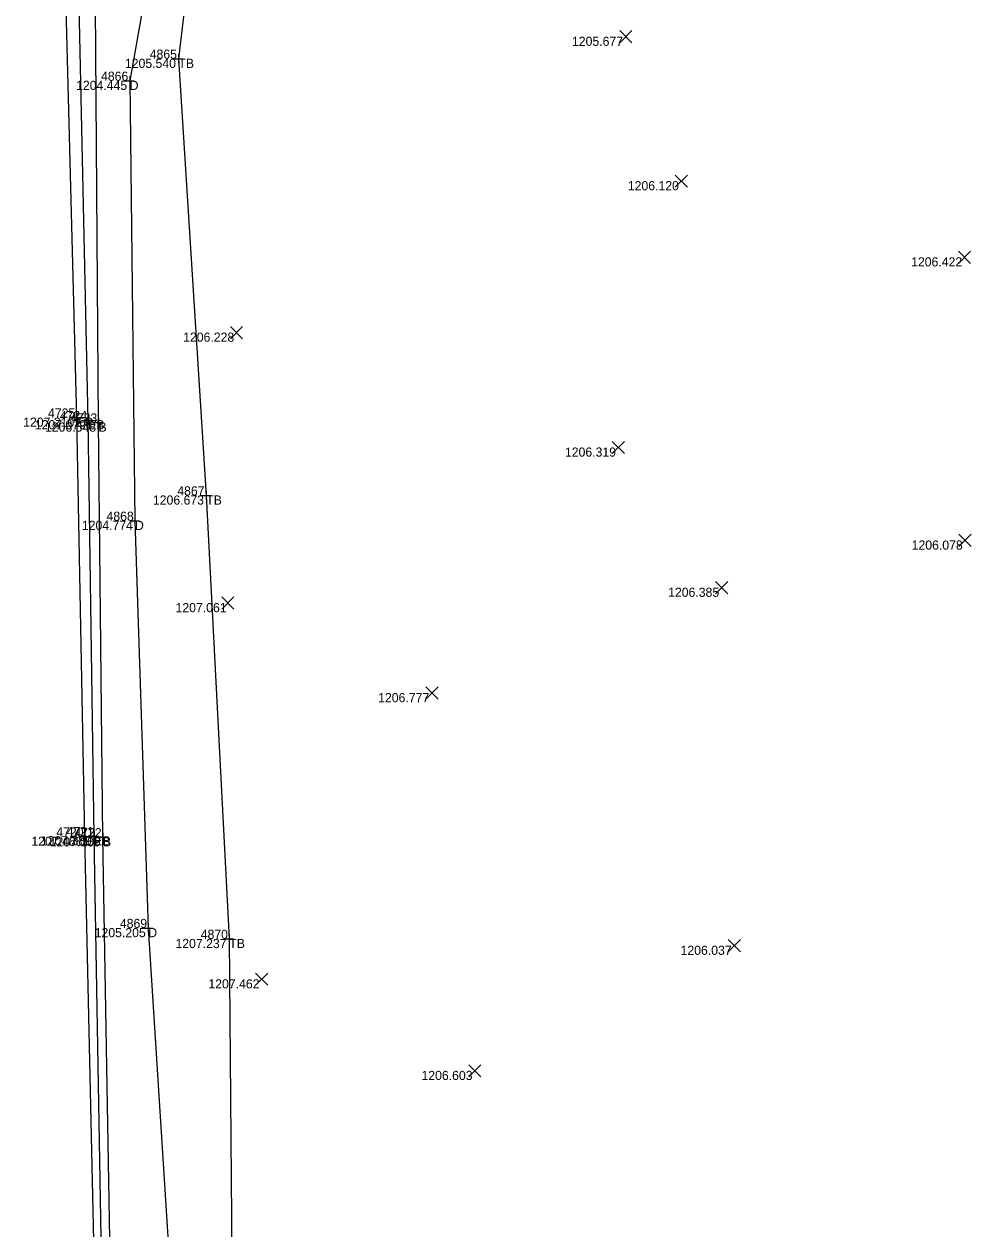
# Model space of a CAD drawing. Extents: x 2044996 to 2050343, y 455232 to 458054.
# Drawn here: x 2047639.9 to 2047743.9, y 456784 to 456915.7 of the extents above; entities that cross this region are included whole.
import ezdxf

# ---------------------------------------------------------------- set-up
doc = ezdxf.new("R2010")
doc.units = 0
for name, color, linetype in [('DR_X_Ditch', 7, 'Continuous'), ('DT_X_Contour_Minor', 7, 'Continuous'), ('DT_X_Contour_Text', 7, 'Continuous'), ('DT_X_Spot_Elev', 7, 'Continuous'), ('DT_X_Triangles', 7, 'Continuous'), ('DT_X_Void', 7, 'Continuous'), ('PV_X_EOP', 7, 'Continuous'), ('PV_X_Shoulder_Aggregate', 7, 'Continuous'), ('SV_X_Break_Lines', 7, 'Continuous'), ('SV_X_Top_of_Bank', 7, 'Continuous')]:
    doc.layers.add(name, color=color, linetype=linetype)

msp = doc.modelspace()

# ---------------------------------------------------------------- linework, layer by layer
at = {"layer": 'DR_X_Ditch'}
msp.add_lwpolyline([(2047944.96, 456861.76), (2047899.25, 456878.16), (2047861.64, 456891.96), (2047815.35, 456909.09), (2047774.86, 456921.86), (2047729.93, 456938.25), (2047691.42, 456950.76), (2047669.22, 456956.37), (2047658.75, 456950.98), (2047651.4, 456909.49), (2047651.98, 456861.4), (2047653.43, 456816.89), (2047656.94, 456761.43), (2047657.83, 456718.94), (2047659.36, 456677.43), (2047660.77, 456628.12), (2047661.37, 456577.1), (2047662.68, 456519.59), (2047665.25, 456466.46), (2047666.16, 456418.54), (2047665.56, 456406.95)], dxfattribs=at)
at = {"layer": 'DT_X_Spot_Elev'}
for p, q in [((2047704.92, 456913.64), (2047706.26, 456914.98)), ((2047704.92, 456914.98), (2047706.26, 456913.64)), ((2047710.98, 456897.86), (2047712.31, 456899.19)), ((2047710.98, 456899.19), (2047712.31, 456897.86)), ((2047741.91, 456889.53), (2047743.25, 456890.87)), ((2047741.91, 456890.87), (2047743.25, 456889.53)), ((2047662.41, 456881.3), (2047663.74, 456882.64)), ((2047662.41, 456882.64), (2047663.74, 456881.3)), ((2047704.1, 456868.74), (2047705.43, 456870.08)), ((2047704.1, 456870.08), (2047705.43, 456868.74)), ((2047741.98, 456858.59), (2047743.31, 456859.92)), ((2047741.98, 456859.92), (2047743.31, 456858.59)), ((2047715.39, 456853.43), (2047716.73, 456854.76)), ((2047715.39, 456854.76), (2047716.73, 456853.43)), ((2047661.46, 456851.75), (2047662.79, 456853.08)), ((2047661.46, 456853.08), (2047662.79, 456851.75)), ((2047683.75, 456841.91), (2047685.08, 456843.24)), ((2047683.75, 456843.24), (2047685.08, 456841.91)), ((2047716.78, 456814.29), (2047718.11, 456815.63)), ((2047716.78, 456815.63), (2047718.11, 456814.29)), ((2047665.16, 456810.63), (2047666.5, 456811.96)), ((2047665.16, 456811.96), (2047666.5, 456810.63)), ((2047688.43, 456800.61), (2047689.76, 456801.95)), ((2047688.43, 456801.95), (2047689.76, 456800.61))]:
    msp.add_line(p, q, dxfattribs=at)
at = {"layer": 'DT_X_Void'}
for p, q in [((2047656.22, 456911.9), (2047657.22, 456911.9)), ((2047656.72, 456912.4), (2047656.72, 456911.4)), ((2047656.72, 456911.9), (2047656.72, 456911.9)), ((2047651.4, 456909.99), (2047651.4, 456908.99)), ((2047650.9, 456909.49), (2047651.9, 456909.49)), ((2047651.4, 456909.49), (2047651.4, 456909.49)), ((2047645.61, 456873.18), (2047645.61, 456872.18)), ((2047645.11, 456872.68), (2047646.11, 456872.68)), ((2047645.61, 456872.68), (2047645.61, 456872.68)), ((2047646.36, 456872.4), (2047647.36, 456872.4)), ((2047646.86, 456872.9), (2047646.86, 456871.9)), ((2047646.86, 456872.4), (2047646.86, 456872.4)), ((2047647.49, 456872.14), (2047648.49, 456872.14)), ((2047647.99, 456872.64), (2047647.99, 456871.64)), ((2047647.99, 456872.14), (2047647.99, 456872.14)), ((2047659.26, 456864.17), (2047660.26, 456864.17)), ((2047659.76, 456864.67), (2047659.76, 456863.67)), ((2047659.76, 456864.17), (2047659.76, 456864.17)), ((2047651.48, 456861.4), (2047652.48, 456861.4)), ((2047651.98, 456861.9), (2047651.98, 456860.9)), ((2047651.98, 456861.4), (2047651.98, 456861.4)), ((2047646.5, 456827.38), (2047646.5, 456826.38)), ((2047647.51, 456827.43), (2047647.51, 456826.43)), ((2047648.48, 456827.31), (2047648.48, 456826.31)), ((2047646, 456826.88), (2047647, 456826.88)), ((2047646.5, 456826.88), (2047646.5, 456826.88)), ((2047647.01, 456826.93), (2047648.01, 456826.93)), ((2047647.51, 456826.93), (2047647.51, 456826.93)), ((2047647.98, 456826.81), (2047648.98, 456826.81)), ((2047648.48, 456826.81), (2047648.48, 456826.81)), ((2047652.93, 456816.89), (2047653.93, 456816.89)), ((2047653.43, 456817.39), (2047653.43, 456816.39)), ((2047653.43, 456816.89), (2047653.43, 456816.89)), ((2047661.78, 456815.7), (2047662.78, 456815.7)), ((2047662.28, 456816.2), (2047662.28, 456815.2)), ((2047662.28, 456815.7), (2047662.28, 456815.7))]:
    msp.add_line(p, q, dxfattribs=at)
at = {"layer": 'PV_X_EOP'}
for p, q in [((2047645.61, 456872.68), (2047644.48, 456917.41)), ((2047646.5, 456826.88), (2047645.61, 456872.68)), ((2047647.56, 456778.58), (2047646.5, 456826.88))]:
    msp.add_line(p, q, dxfattribs=at)
at = {"layer": 'PV_X_Shoulder_Aggregate'}
msp.add_lwpolyline([(2047651.94, 456638.93), (2047650.86, 456688.18), (2047649.6, 456733), (2047648.37, 456778.91), (2047647.51, 456826.93), (2047646.86, 456872.4), (2047645.87, 456917.72), (2047645.01, 456938.98), (2047644.95, 456952.82), (2047645.89, 456959.85), (2047646.68, 456960.97), (2047650.24, 456962.76), (2047655.73, 456966.3), (2047657.7, 456966.84), (2047664.7, 456965.75), (2047672.59, 456964.54), (2047677.71, 456963.33), (2047718.66, 456948.27), (2047759.49, 456933.93)], dxfattribs=at)
at = {"layer": 'SV_X_Break_Lines'}
msp.add_lwpolyline([(2047658.43, 456406.25), (2047657.57, 456454.16), (2047657.12, 456499.13), (2047656.02, 456546.18), (2047654.76, 456590.52), (2047653.67, 456638.77), (2047652.84, 456687.95), (2047651.32, 456732.84), (2047649.31, 456778.74), (2047648.48, 456826.81), (2047647.99, 456872.14), (2047647.65, 456917.64), (2047648.11, 456940.22), (2047652.79, 456955.84)], dxfattribs=at)
at = {"layer": 'SV_X_Top_of_Bank'}
msp.add_lwpolyline([(2047942.14, 456857.99), (2047898.01, 456872.36), (2047859.06, 456885.19), (2047815.47, 456901.27), (2047771.85, 456916.42), (2047729.97, 456932.49), (2047688.22, 456947.3), (2047669.99, 456955.17), (2047661.07, 456948.62), (2047656.72, 456911.9), (2047659.76, 456864.17), (2047662.28, 456815.7), (2047662.72, 456763.39), (2047662.48, 456719.38), (2047665.2, 456677.14), (2047665.7, 456629.87), (2047667.28, 456578.15), (2047668.69, 456520.88), (2047669.88, 456466.8), (2047671, 456408.28)], dxfattribs=at)

# ---------------------------------------------------------------- texts
at = {"layer": 'DT_X_Contour_Minor'}
for s, p in [('1205.677', (2047699.71, 456913.31)), ('1205.540', (2047650.88, 456910.9)), ('1204.445', (2047645.55, 456908.49)), ('1206.120', (2047705.81, 456897.52)), ('1206.422', (2047736.75, 456889.2)), ('1206.228', (2047657.24, 456880.97)), ('1207.210', (2047639.77, 456871.68)), ('1207.079', (2047641.04, 456871.4)), ('1206.548', (2047642.15, 456871.14)), ('1206.319', (2047698.94, 456868.41)), ('1206.673', (2047653.94, 456863.17)), ('1204.774', (2047646.18, 456860.4)), ('1206.078', (2047736.81, 456858.25)), ('1206.385', (2047710.21, 456853.09)), ('1207.061', (2047656.41, 456851.41)), ('1206.777', (2047678.54, 456841.57)), ('1207.488', (2047640.66, 456825.88)), ('1207.389', (2047641.69, 456825.93)), ('1207.109', (2047642.66, 456825.81)), ('1205.205', (2047647.58, 456815.89)), ('1207.237', (2047656.4, 456814.7)), ('1206.037', (2047711.57, 456813.96)), ('1207.462', (2047660, 456810.29)), ('1206.603', (2047683.27, 456800.28))]:
    msp.add_text(s, height=1, dxfattribs=at).set_placement(p)
at = {"layer": 'DT_X_Contour_Text'}
for s, p in [('TB', (2047656.72, 456910.9)), ('D', (2047651.4, 456908.49)), ('EP', (2047645.61, 456871.68)), ('EB', (2047646.86, 456871.4)), ('B', (2047647.99, 456871.14)), ('TB', (2047659.76, 456863.17)), ('D', (2047651.98, 456860.4)), ('EP', (2047646.5, 456825.88)), ('EB', (2047647.51, 456825.93)), ('B', (2047648.48, 456825.81)), ('D', (2047653.43, 456815.89)), ('TB', (2047662.28, 456814.7))]:
    msp.add_text(s, height=1, dxfattribs=at).set_placement(p)
at = {"layer": 'DT_X_Triangles'}
for s, p in [('4865', (2047653.59, 456911.9)), ('4866', (2047648.27, 456909.49)), ('4725', (2047642.48, 456872.68)), ('4724', (2047643.77, 456872.4)), ('4723', (2047644.88, 456872.14)), ('4867', (2047656.6, 456864.17)), ('4868', (2047648.87, 456861.4)), ('4720', (2047643.38, 456826.88)), ('4721', (2047644.51, 456826.93)), ('4722', (2047645.36, 456826.81)), ('4869', (2047650.33, 456816.89)), ('4870', (2047659.16, 456815.7))]:
    msp.add_text(s, height=1, dxfattribs=at).set_placement(p)

doc.saveas('drawing.dxf')
